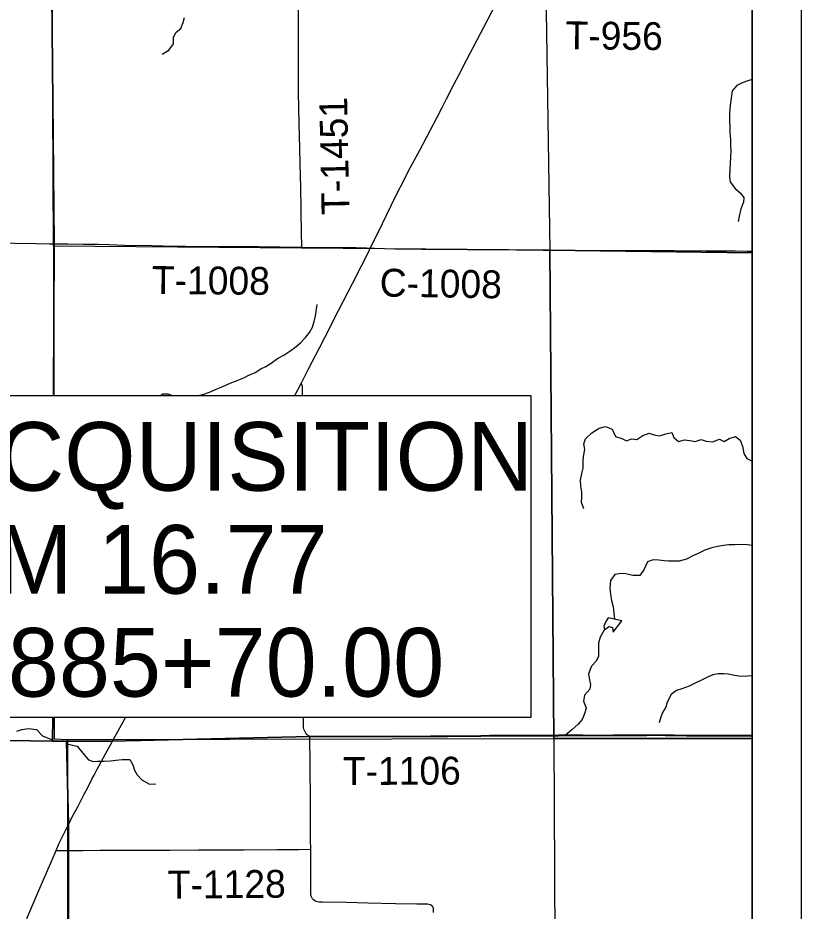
# Model space of a CAD drawing. Extents: x 0 to 34, y 0 to 22.
# Drawn here: x 7.402 to 9, y 17.915 to 19.737 of the extents above; entities that cross this region are included whole.
import ezdxf

# ---------------------------------------------------------------- set-up
doc = ezdxf.new("R2010")
doc.units = 0
for name, color, linetype in [('Default', 7, 'Continuous'), ('GM_X_County_Road', 7, 'Continuous'), ('GM_X_County_Road_Text', 7, 'Continuous'), ('GM_X_Minor_Lake', 7, 'Continuous'), ('GM_X_Minor_River', 7, 'Continuous'), ('GM_X_Section', 7, 'Continuous'), ('GM_X_State_Route', 7, 'Continuous'), ('GM_X_Township_Road', 7, 'Continuous'), ('GM_X_Township_Road_Text', 7, 'Continuous'), ('SH_Cut_Line', 7, 'Continuous'), ('SH_Data', 7, 'Continuous')]:
    doc.layers.add(name, color=color, linetype=linetype)

msp = doc.modelspace()

# ---------------------------------------------------------------- linework, layer by layer
at = {"layer": 'Default'}
for points in [[(6.2148, 18.2783), (6.4787, 18.2762), (7.4731, 18.2617), (7.4732, 18.3097), (6.7366, 18.3097), (6.7366, 18.9662), (7.4751, 18.9662), (7.476, 19.2764), (7.4665, 20.2923), (7.4609, 20.9), (3.3847, 20.9)], [(7.4665, 20.2923), (7.476, 19.2764), (7.4751, 18.9662), (8.4483, 18.9662), (8.4483, 18.3097), (7.4732, 18.3097), (7.4731, 18.2617), (7.5011, 18.2616), (7.5945, 18.2615), (7.9975, 18.2712), (8.0235, 18.271), (8.0764, 18.2712), (8.1044, 18.2711), (8.1479, 18.2712), (8.1728, 18.2714), (8.1914, 18.2712), (8.2442, 18.2715), (8.2785, 18.2717), (8.3251, 18.272), (8.3466, 18.2724), (8.3652, 18.2727), (8.452, 18.273), (8.5049, 18.2739), (8.5329, 18.2737), (8.5546, 18.2734), (8.5764, 18.2733), (8.6168, 18.2739), (8.6448, 18.2737), (8.6634, 18.2735), (8.6852, 18.2738), (8.7039, 18.2739), (8.7225, 18.2738), (8.7412, 18.2734), (8.766, 18.273), (8.7847, 18.273), (8.8282, 18.2732), (8.878, 18.2729), (8.9, 18.2728), (8.9, 20.9)], [(7.5053, 17.3084), (7.5051, 18.039), (7.5056, 18.0926), (7.5011, 18.2616), (7.4731, 18.2617), (6.4787, 18.2762), (6.2148, 18.2783), (6.2148, 17.662)], [(8.9, 14.1), (8.9, 18.2728), (8.878, 18.2729), (8.8282, 18.2732), (8.7847, 18.273), (8.766, 18.273), (8.7412, 18.2734), (8.7225, 18.2738), (8.7039, 18.2739), (8.6852, 18.2738), (8.6634, 18.2735), (8.6448, 18.2737), (8.6168, 18.2739), (8.5764, 18.2733), (8.5546, 18.2734), (8.5329, 18.2737), (8.5049, 18.2739), (8.452, 18.273), (8.3652, 18.2727), (8.3466, 18.2724), (8.3251, 18.272), (8.2785, 18.2717), (8.2442, 18.2715), (8.1914, 18.2712), (8.1728, 18.2714), (8.1479, 18.2712), (8.1044, 18.2711), (8.0764, 18.2712), (8.0235, 18.271), (7.9975, 18.2712), (7.5945, 18.2615), (7.5011, 18.2616), (7.5056, 18.0926), (7.5051, 18.039), (7.5053, 17.3084)]]:
    msp.add_lwpolyline(points, dxfattribs=at)
for points in [[(8.9, 19.2576), (8.9, 20.2798), (8.4715, 20.2822), (8.487, 19.2631)], [(8.9, 18.2671), (8.9, 19.2576), (8.487, 19.2631), (8.4952, 18.2672)], [(8.9, 17.2976), (8.9, 18.2671), (8.4952, 18.2672), (8.5004, 17.303)]]:
    msp.add_lwpolyline(points, close=True, dxfattribs=at)
at = {"layer": 'GM_X_County_Road'}
msp.add_lwpolyline([(8.1211, 19.2667), (8.1299, 19.2667), (8.1712, 19.2658), (8.226, 19.2652), (8.3184, 19.2642), (8.4178, 19.2633), (8.4427, 19.2633), (8.4738, 19.2629), (8.5048, 19.2626), (8.539, 19.2626), (8.5949, 19.2621), (8.6198, 19.262), (8.6509, 19.2625), (8.6664, 19.2623), (8.6788, 19.2622), (8.7409, 19.2619), (8.8062, 19.2616), (8.8653, 19.2614), (8.8901, 19.2612), (8.9, 19.2611)], dxfattribs=at)
at = {"layer": 'GM_X_Minor_Lake'}
for points in [[(8.606, 18.5128), (8.6019, 18.5053), (8.5973, 18.4958), (8.5988, 18.4889), (8.6083, 18.4954), (8.6151, 18.4931), (8.6167, 18.484), (8.6345, 18.5071)], [(8.6345, 18.5071), (8.606, 18.5128)]]:
    msp.add_lwpolyline(points, dxfattribs=at)
at = {"layer": 'GM_X_Minor_River'}
for points in [[(7.6964, 19.663), (7.7104, 19.6706), (7.7196, 19.6839), (7.7196, 19.6972), (7.7253, 19.7078), (7.7347, 19.715), (7.7393, 19.7271), (7.7423, 19.7374)], [(8.9, 19.6107), (8.8895, 19.6073), (8.8781, 19.6036), (8.8687, 19.599), (8.8595, 19.5876), (8.8573, 19.5732), (8.8554, 19.558), (8.8538, 19.5425), (8.8538, 19.5284), (8.8542, 19.5129), (8.8546, 19.5019), (8.8557, 19.4886), (8.8561, 19.4753), (8.8565, 19.4655), (8.8561, 19.4533), (8.8553, 19.4389), (8.8545, 19.4283), (8.8538, 19.4123), (8.8549, 19.4025), (8.8644, 19.3896), (8.8757, 19.3797), (8.8833, 19.3702), (8.8826, 19.3607), (8.8769, 19.3475), (8.8738, 19.3323), (8.8712, 19.3217)], [(7.77, 18.9662), (7.7837, 18.9698), (7.7962, 18.9747), (7.8068, 18.9796), (7.8201, 18.9849), (7.8349, 18.9914), (7.8493, 18.9971), (7.863, 19.0024), (7.8736, 19.0077), (7.8865, 19.0134), (7.8979, 19.0206), (7.9077, 19.0259), (7.9187, 19.0327), (7.9316, 19.0418), (7.9445, 19.0486), (7.9567, 19.0566), (7.9696, 19.0661), (7.979, 19.0736), (7.9889, 19.0846), (7.9969, 19.0949), (8.003, 19.1059), (8.0067, 19.1173), (8.009, 19.129), (8.0113, 19.1423), (8.0125, 19.1518)], [(7.6933, 18.9662), (7.6976, 18.9698), (7.7082, 18.9698), (7.7177, 18.9664), (7.7182, 18.9662)], [(8.5565, 18.7356), (8.5516, 18.7485), (8.5523, 18.7599), (8.5527, 18.7694), (8.5508, 18.7815), (8.5497, 18.7937), (8.5527, 18.8077), (8.5554, 18.8183), (8.555, 18.8316), (8.5558, 18.8418), (8.5584, 18.8563), (8.5565, 18.8677), (8.56, 18.8779), (8.5729, 18.8904), (8.588, 18.8999), (8.6006, 18.9033), (8.6146, 18.898), (8.6214, 18.8832), (8.6339, 18.8786), (8.6438, 18.8741), (8.6536, 18.8778), (8.6646, 18.8767), (8.6772, 18.885), (8.6897, 18.89), (8.6999, 18.8862), (8.7113, 18.8843), (8.7238, 18.888), (8.7363, 18.8907), (8.7401, 18.8808), (8.75, 18.8725), (8.7621, 18.8763), (8.7731, 18.8747), (8.7841, 18.8728), (8.7959, 18.8766), (8.8065, 18.8736), (8.8194, 18.8717), (8.8334, 18.8774), (8.8433, 18.8728), (8.8535, 18.8789), (8.866, 18.8826), (8.8759, 18.8754), (8.8804, 18.8629), (8.8834, 18.8481), (8.8891, 18.8382), (8.899, 18.8333), (8.9, 18.8333)], [(8.9, 18.6604), (8.8909, 18.6622), (8.878, 18.6626), (8.8648, 18.6622), (8.8526, 18.6618), (8.8413, 18.6607), (8.8291, 18.6588), (8.8177, 18.6561), (8.8037, 18.6508), (8.7897, 18.644), (8.7802, 18.6399), (8.7658, 18.633), (8.751, 18.6289), (8.74, 18.6285), (8.7297, 18.6289), (8.7203, 18.6296), (8.71, 18.6308), (8.6983, 18.6316), (8.6865, 18.6274), (8.6801, 18.6126), (8.6706, 18.5997), (8.6569, 18.5997), (8.6425, 18.6027), (8.633, 18.6035), (8.6197, 18.6016), (8.611, 18.5891), (8.6095, 18.5739), (8.6114, 18.5603), (8.6133, 18.5485), (8.6167, 18.5356), (8.6192, 18.5102)], [(8.5988, 18.4889), (8.5901, 18.4734), (8.5863, 18.4612), (8.5867, 18.448), (8.5863, 18.4347), (8.5821, 18.4244), (8.5722, 18.4146), (8.5662, 18.3987), (8.5684, 18.3869), (8.57, 18.377), (8.5692, 18.3675), (8.5578, 18.355), (8.5563, 18.3433), (8.5616, 18.3296), (8.5589, 18.3194), (8.5532, 18.3057), (8.5453, 18.2962), (8.532, 18.2845), (8.5187, 18.2731)], [(8.9, 18.3947), (8.8908, 18.3939), (8.8772, 18.3935), (8.8608, 18.3962), (8.8514, 18.3981), (8.8419, 18.3989), (8.8309, 18.3985), (8.8199, 18.3966), (8.81, 18.3928), (8.7979, 18.3868), (8.7854, 18.3807), (8.7713, 18.3739), (8.7569, 18.3682), (8.7455, 18.3648), (8.7349, 18.3568), (8.7269, 18.3413), (8.7239, 18.331), (8.7175, 18.32), (8.7129, 18.3083), (8.7106, 18.2988)], [(7.4001, 18.2817), (7.41, 18.285), (7.4237, 18.2876), (7.4404, 18.2853), (7.4521, 18.2723), (7.474, 18.2635)], [(7.5021, 18.2555), (7.5084, 18.2547), (7.5232, 18.2513), (7.5345, 18.2372), (7.5459, 18.2236), (7.5554, 18.2201), (7.5649, 18.2205), (7.5785, 18.2209), (7.5914, 18.2216), (7.602, 18.2224), (7.6149, 18.2239), (7.6305, 18.2243), (7.6365, 18.2133), (7.6403, 18.2023), (7.6456, 18.1928), (7.6551, 18.1829), (7.6706, 18.1738), (7.6835, 18.1742)]]:
    msp.add_lwpolyline(points, dxfattribs=at)
at = {"layer": 'GM_X_Section'}
for points in [[(8.4715, 20.2822), (8.487, 19.2631), (7.4747, 19.2711), (7.4702, 20.2887)], [(7.4764, 18.3097), (7.4765, 18.2661), (7.5042, 18.265), (8.4952, 18.2672), (8.487, 19.2631), (7.4747, 19.2711), (7.4752, 18.9662), (8.4483, 18.9662), (8.4483, 18.3097)], [(8.4952, 18.2672), (8.5004, 17.303), (7.5048, 17.3031), (7.5042, 18.265)]]:
    msp.add_lwpolyline(points, close=True, dxfattribs=at)
at = {"layer": 'GM_X_State_Route'}
for points in [[(7.9673, 18.9662), (7.9803, 18.9909), (7.995, 19.0212), (8.0167, 19.0625), (8.0281, 19.0846), (8.0565, 19.1399), (8.0849, 19.1951), (8.1033, 19.2311), (8.1172, 19.2589), (8.1211, 19.2667), (8.1267, 19.2785), (8.1459, 19.3175), (8.1636, 19.3538), (8.1788, 19.3844), (8.1858, 19.3983), (8.1986, 19.4231), (8.2219, 19.467), (8.2436, 19.5083), (8.2567, 19.533), (8.2681, 19.5551), (8.2766, 19.5717), (8.291, 19.5992), (8.3024, 19.6213), (8.3182, 19.6516), (8.3529, 19.7176), (8.3775, 19.7644)], [(7.5947, 18.2609), (7.6033, 18.2767), (7.6169, 18.3011), (7.6216, 18.3097)], [(7.5058, 18.0921), (7.5132, 18.1069), (7.5248, 18.1288), (7.5377, 18.1535), (7.5447, 18.1673), (7.5533, 18.1838), (7.5576, 18.1921), (7.5635, 18.203), (7.5722, 18.2194), (7.5811, 18.2358), (7.5944, 18.2603), (7.5947, 18.2609)], [(7.4205, 17.8995), (7.4448, 17.9567), (7.4801, 18.0384), (7.4867, 18.0533), (7.4961, 18.0728), (7.5002, 18.0809), (7.5058, 18.0921)]]:
    msp.add_lwpolyline(points, dxfattribs=at)
at = {"layer": 'GM_X_Township_Road'}
for points in [[(7.9815, 19.2688), (7.9813, 19.2753), (7.9808, 19.2939), (7.9801, 19.3467), (7.9794, 19.3902), (7.9788, 19.415), (7.9781, 19.4399), (7.9775, 19.471), (7.9762, 19.5207), (7.9754, 19.5548), (7.9749, 19.5828), (7.9744, 19.617), (7.9743, 19.648), (7.9743, 19.6915), (7.9743, 19.735), (7.9736, 19.797)], [(6.6547, 19.2848), (6.6617, 19.2847), (6.6927, 19.2844), (6.7269, 19.2844), (6.7642, 19.2841), (6.7891, 19.284), (6.8171, 19.2835), (6.845, 19.2831), (6.8885, 19.2826), (6.932, 19.2824), (6.96, 19.2821), (7.0097, 19.2815), (7.0532, 19.281), (7.0936, 19.2804), (7.1806, 19.2798), (7.249, 19.2792), (7.2863, 19.279), (7.3205, 19.2785), (7.3515, 19.278), (7.395, 19.2772), (7.4385, 19.2763), (7.4665, 19.2759), (7.4762, 19.2758)], [(7.4762, 19.2758), (7.5046, 19.2756), (7.5357, 19.2752), (7.5668, 19.2749), (7.5885, 19.2743), (7.6196, 19.2731), (7.6756, 19.2721), (7.7222, 19.2713), (7.7439, 19.2709), (7.7781, 19.2707), (7.803, 19.2703), (7.834, 19.2705), (7.8527, 19.2704), (7.8931, 19.2703), (7.9367, 19.2694), (7.9677, 19.2689), (7.9815, 19.2688)], [(7.9815, 19.2688), (8.005, 19.2686), (8.0268, 19.2683), (8.0641, 19.2682), (8.0921, 19.2682), (8.1131, 19.2674), (8.1211, 19.2667)], [(7.9825, 18.9662), (7.9828, 18.9768), (7.9827, 18.9823), (7.9826, 18.9849), (7.982, 18.9876), (7.9803, 18.9909)], [(7.9977, 18.2707), (7.995, 18.2722), (7.9933, 18.2735), (7.9917, 18.2753), (7.9897, 18.2777), (7.988, 18.2803), (7.9867, 18.2831), (7.9856, 18.286), (7.985, 18.289), (7.9846, 18.2921), (7.9846, 18.2982), (7.9847, 18.3092), (7.9847, 18.3097)], [(7.9977, 18.2707), (8.0237, 18.2705), (8.0766, 18.2707), (8.1046, 18.2706), (8.1481, 18.2707), (8.173, 18.2708), (8.1916, 18.2706), (8.2445, 18.271), (8.2787, 18.2712), (8.3253, 18.2714), (8.3468, 18.2719), (8.3655, 18.2721), (8.4522, 18.2722), (8.5049, 18.2725), (8.5331, 18.2731), (8.5549, 18.2728), (8.5766, 18.2727), (8.6171, 18.2728), (8.645, 18.2732), (8.6637, 18.273), (8.6854, 18.2732), (8.7041, 18.2734), (8.7227, 18.2732), (8.7414, 18.2728), (8.7662, 18.2725), (8.7849, 18.2724), (8.8284, 18.2726), (8.8782, 18.2724), (8.9, 18.2723)], [(7.9996, 18.0409), (7.9993, 18.0604), (7.999, 18.0975), (7.9988, 18.1381), (7.9983, 18.2131), (7.9977, 18.2707)], [(7.4801, 18.0384), (7.4885, 18.0385), (7.5, 18.0384), (7.5053, 18.0385)], [(7.5053, 18.0385), (7.5352, 18.0384), (7.5693, 18.039), (7.6096, 18.0389), (7.6654, 18.0392), (7.7119, 18.0391), (7.7708, 18.0398), (7.8296, 18.0401), (7.8637, 18.0401), (7.9319, 18.0405), (7.9753, 18.0404), (7.9996, 18.0409)], [(8.2502, 17.9118), (8.2502, 17.918), (8.2497, 17.9211), (8.2484, 17.9238), (8.2463, 17.9261), (8.2436, 17.9276), (8.2406, 17.9283), (8.2375, 17.9287), (8.2157, 17.9289), (8.1722, 17.93), (8.1163, 17.931), (8.0727, 17.9321), (8.0229, 17.9329), (8.0167, 17.9332), (8.0136, 17.9337), (8.0106, 17.9345), (8.0078, 17.9358), (8.0054, 17.9377), (8.0033, 17.94), (8.0018, 17.9426), (8.0007, 17.9455), (8, 17.9486), (7.9996, 17.9517), (7.9995, 17.9579), (7.9996, 17.9735), (7.9997, 18.0108), (7.9996, 18.0409)]]:
    msp.add_lwpolyline(points, dxfattribs=at)
at = {"layer": 'SH_Cut_Line'}
for points in [[(7.5053, 17.3084), (7.5051, 18.039), (7.5056, 18.0926), (7.5011, 18.2616), (7.4731, 18.2617), (7.4732, 18.3097), (6.7366, 18.3097), (6.7366, 18.9662), (7.4751, 18.9662), (7.476, 19.2764), (7.4665, 20.2923), (7.4609, 20.9), (2.1, 20.9), (2.1, 14.1)], [(8.9, 14.1), (8.9, 20.9), (7.4609, 20.9), (7.4665, 20.2923), (7.476, 19.2764), (7.4751, 18.9662), (8.4483, 18.9662), (8.4483, 18.3097), (7.4732, 18.3097), (7.4731, 18.2617), (7.5011, 18.2616), (7.5056, 18.0926), (7.5051, 18.039), (7.5053, 17.3084)]]:
    msp.add_lwpolyline(points, dxfattribs=at)
at = {"layer": 'SH_Data'}
for p, q in [((9, 21), (9, 14)), ((8.9, 20.9), (8.9, 14.1))]:
    msp.add_line(p, q, dxfattribs=at)

# ---------------------------------------------------------------- texts
at = {"layer": 'Default'}
for s, p in [('END ACQUISITION', (6.7893, 18.7723)), ('SLM 16.77', (7.1286, 18.5623)), ('STA. 885+70.00', (6.9136, 18.3523))]:
    msp.add_text(s, height=0.14, dxfattribs=at).set_placement(p)
at = {"layer": 'GM_X_County_Road_Text'}
msp.add_text('C-1008', height=0.05682, rotation=359.0864, dxfattribs=at).set_placement((8.1399, 19.1685))
at = {"layer": 'GM_X_Township_Road_Text'}
for s, rotation, p in [('T-956', 359.4438, (8.5191, 19.6728)), ('T-1451', 91.1642, (8.0786, 19.3352)), ('T-1008', 359.5283, (7.6753, 19.1737)), ('T-1106', 0.242, (8.0651, 18.172)), ('T-1128', 0.4687, (7.7081, 17.9403))]:
    msp.add_text(s, height=0.05682, rotation=rotation, dxfattribs=at).set_placement(p)

doc.saveas('drawing.dxf')
